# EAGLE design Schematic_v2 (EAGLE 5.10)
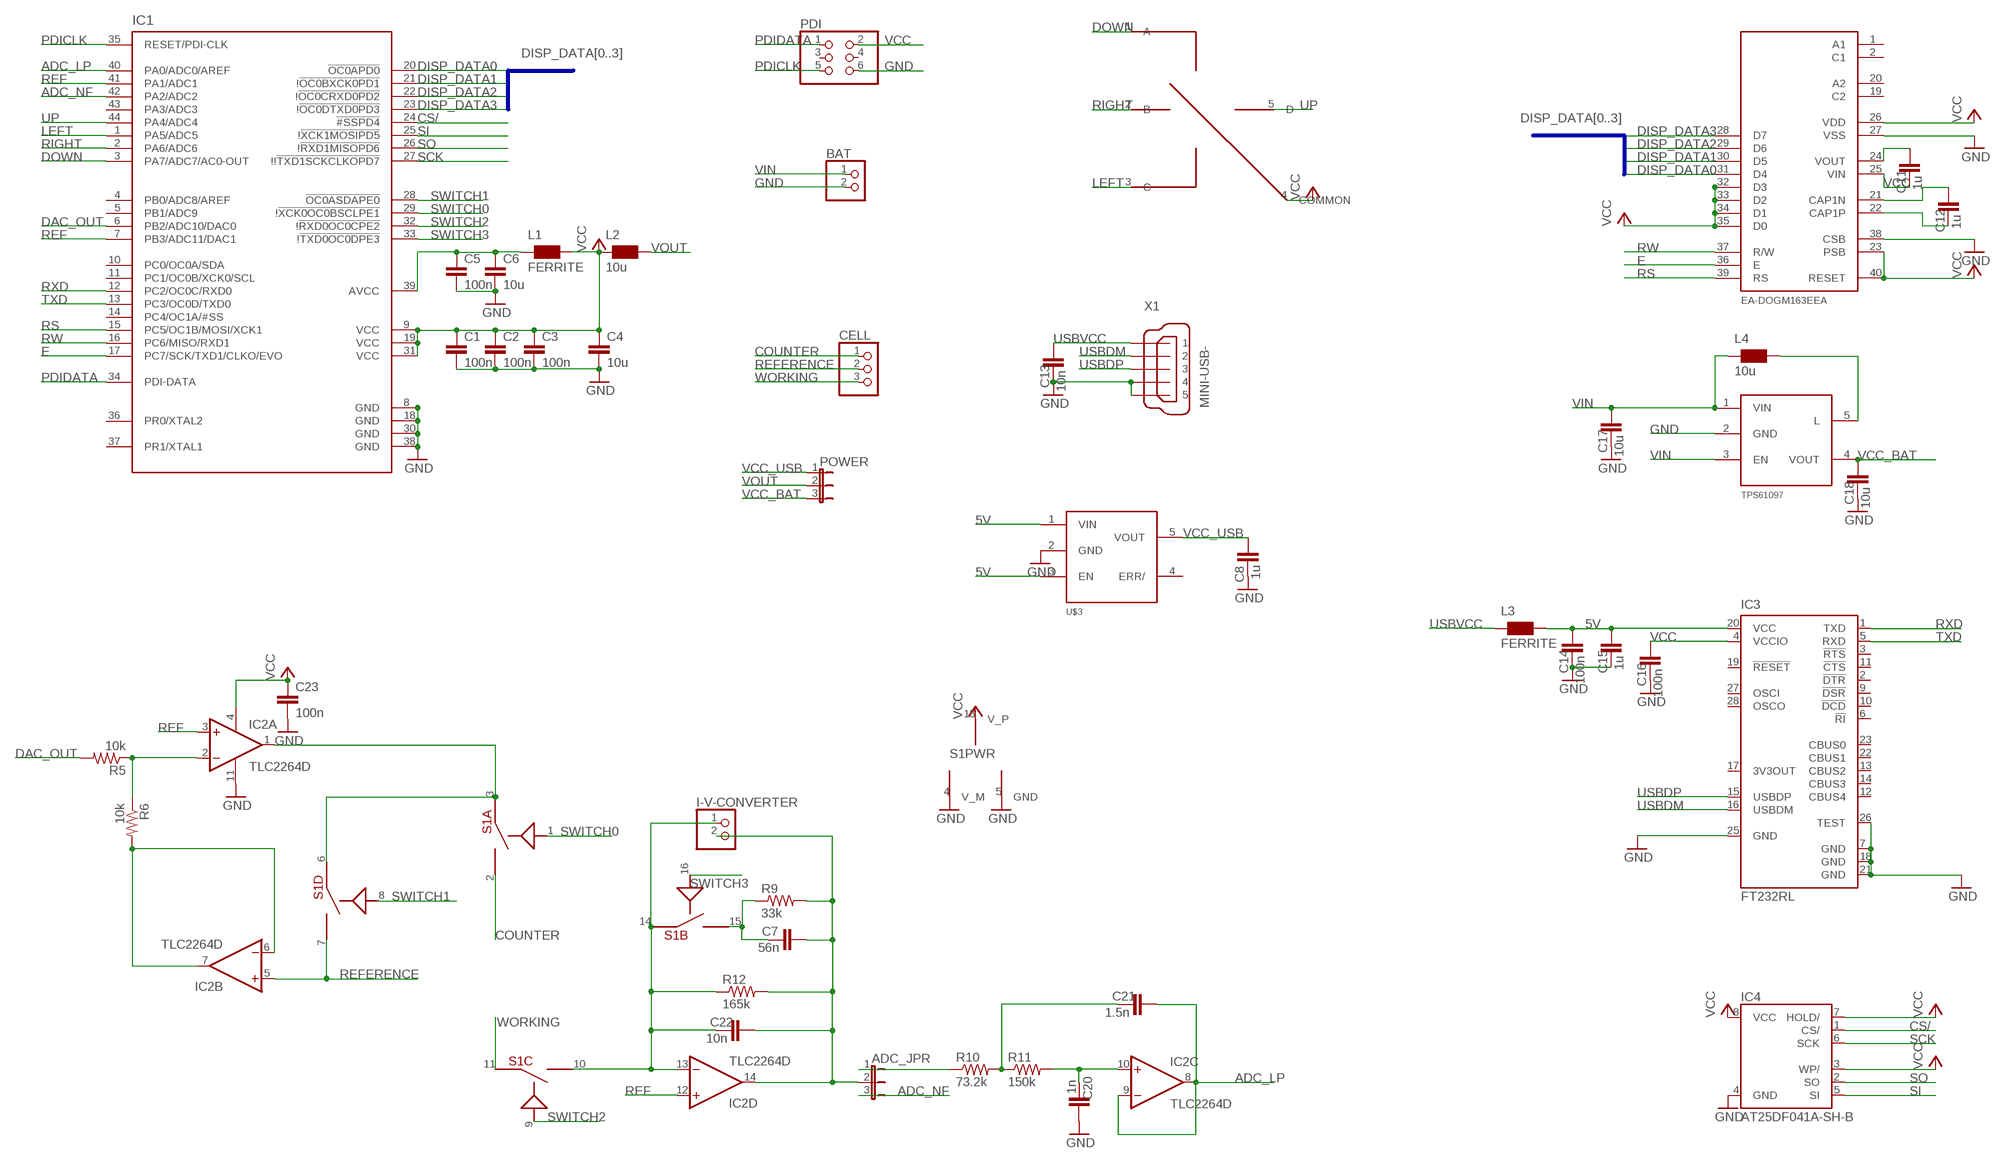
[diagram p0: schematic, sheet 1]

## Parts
ADC_JPR  JP2E  [JP2]
BAT  PINHD-1X2  [1X02]
C1  100n  C-EUC0805  [C0805]
C2  100n  C-EUC0805  [C0805]
C3  100n  C-EUC0805  [C0805]
C4  10u  C-EUC0805  [C0805]
C5  100n  C-EUC0805  [C0805]
C6  10u  C-EUC0805  [C0805]
C7  56n  C-EUC0805  [C0805]
C8  1u  C-EUC0805  [C0805]
C11  1u  C-EUC0805  [C0805]
C12  1u  C-EUC0805  [C0805]
C13  10n  C-EUC0805  [C0805]
C14  100n  C-EUC0805  [C0805]
C15  1u  C-EUC0805  [C0805]
C16  100n  C-EUC0805  [C0805]
C17  10u  C-EUC0805  [C0805]
C18  10u  C-EUC0805  [C0805]
C20  1n  C-EUC0805  [C0805]
C21  1.5n  C-EUC0805  [C0805]
C22  10n  C-EUC0805  [C0805]
C23  100n  C-EUC0805  [C0805]
CELL  PINHD-1X3  [1X03]
I-V-CONVERTER  PINHD-1X2  [1X02]
IC1  AT-XMEGA-XXA4-AU  [QFP80P1200X1200X120-44N]
IC2  TLC2264D  [SO14]
IC3  FT232RL  [SSOP28]
IC4  AT25DF041A-SH-B  [SOIC8]
L1  FERRITE  WE-KIHQ_0805  [WE-KI_0805_B]
L2  10u  WE-KIHQ_0805  [WE-KI_0805_B]
L3  FERRITE  WE-KIHQ_0805  [WE-KI_0805_B]
L4  10u  WE-KIHQ_0805  [WE-KI_0805_B]
PDI  PINHD-2X3  [2X03]
POWER  JP2E  [JP2]
R5  10k  R-US_R0805  [R0805]
R6  10k  R-US_R0805  [R0805]
R9  33k  R-US_R0805  [R0805]
R10  73.2k  R-US_R0805  [R0805]
R11  150k  R-US_R0805  [R0805]
R12  165k  R-US_R0805  [R0805]
S1  DG612  [SOIC16]
TPS61097  DC-DCCONVERTER  [SOT23-5]
U$1  EA_DOG-M_DISPLAY  [E_DOG-M_DISPLAY]
U$2  4DIRSWITCH  [4DIRSWITCH]
U$3  FAN2501  [SOT23-5]
X1  MINI-USB-  [USB-CUSTOM]

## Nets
5V: C14.1 C15.1 IC3.20(VCC) L3.1 U$3.1(VIN) U$3.3(EN)
ADC_LP: C21.1 IC1.40(PA0/ADC0/AREF) IC2.8(C:OUT) IC2.9(C:-IN)
ADC_NF: ADC_JPR.3 IC1.42(PA2/ADC2)
COUNTER: CELL.1 S1.2(A:D)
CS/: IC1.24(!#SSPD4) IC4.1(CS/)
DAC_OUT: IC1.6(PB2/ADC10/DAC0) R5.2
DISP_DATA0: IC1.20(!OC0APD0) U$1.31(D4)
DISP_DATA1: IC1.21(!!OC0BXCK0PD1) U$1.30(D5)
DISP_DATA2: IC1.22(!!OC0CRXD0PD2) U$1.29(D6)
DISP_DATA3: IC1.23(!!OC0DTXD0PD3) U$1.28(D7)
DOWN: IC1.3(PA7/ADC7/AC0-OUT) U$2.1(A)
E: IC1.17(PC7/SCK/TXD1/CLKO/EVO) U$1.36(E)
GND: BAT.2 C1.2 C2.2 C3.2 C4.2 C5.2 C6.2 C8.2 C13.2 C14.2 C15.2 C16.2 C17.2 C18.2 C20.1 C23.2 IC1.8(GND) IC1.18(GND) IC1.30(GND) IC1.38(GND) IC2.11(P:V-) IC3.7(GND) IC3.18(GND) IC3.21(GND) IC3.25(GND) IC3.26(TEST) IC4.4(GND) PDI.6 S1.4(PWR:V_M) S1.5(PWR:GND) TPS61097.2(GND) U$1.27(VSS) U$1.38(CSB) U$3.2(GND) X1.4 X1.5
LEFT: IC1.1(PA5/ADC5) U$2.3(C)
N$3: ADC_JPR.2 C7.1 C22.1 I-V-CONVERTER.2 IC2.14(D:OUT) R9.2 R12.2
N$4: IC2.6(B:-IN) IC2.7(B:OUT) R6.2
N$5: C5.1 C6.1 IC1.39(AVCC) L1.2
N$6: C7.2 R9.1 S1.15(B:D)
N$7: C11.1 U$1.24(VOUT)
N$8: IC2.2(A:-IN) R5.1 R6.1
N$9: C12.1 U$1.21(CAP1N)
N$10: L4.1 TPS61097.5(L)
N$12: C22.2 I-V-CONVERTER.1 IC2.13(D:-IN) R12.1 S1.10(C:D) S1.14(B:S)
N$14: C12.2 U$1.22(CAP1P)
N$16: ADC_JPR.1 R10.1
N$17: C20.2 IC2.10(C:+IN) R11.2
N$19: IC2.1(A:OUT) S1.3(A:S) S1.6(D:S)
N$20: C21.2 R10.2 R11.1
PDICLK: IC1.35(RESET/PDI-CLK) PDI.5
PDIDATA: IC1.34(PDI-DATA) PDI.1
REF: IC1.7(PB3/ADC11/DAC1) IC1.41(PA1/ADC1) IC2.3(A:+IN) IC2.12(D:+IN)
REFERENCE: CELL.2 IC2.5(B:+IN) S1.7(D:D)
RIGHT: IC1.2(PA6/ADC6) U$2.2(B)
RS: IC1.15(PC5/OC1B/MOSI/XCK1) U$1.39(RS)
RW: IC1.16(PC6/MISO/RXD1) U$1.37(R/W)
RXD: IC1.12(PC2/OC0C/RXD0) IC3.1(TXD)
SCK: IC1.27(!!!TXD1SCKCLKOPD7) IC4.6(SCK)
SI: IC1.25(!!XCK1MOSIPD5) IC4.5(SI)
SO: IC1.26(!!RXD1MISOPD6) IC4.2(SO)
SWITCH0: IC1.29(!!XCK0OC0BSCLPE1) S1.1(A:IN)
SWITCH1: IC1.28(!OC0ASDAPE0) S1.8(D:IN)
SWITCH2: IC1.32(!!RXD0OC0CPE2) S1.9(C:IN)
SWITCH3: IC1.33(!!TXD0OC0DPE3) S1.16(B:IN)
TXD: IC1.13(PC3/OC0D/TXD0) IC3.5(RXD)
UP: IC1.44(PA4/ADC4) U$2.5(D)
USBDM: IC3.16(USBDM) X1.2
USBDP: IC3.15(USBDP) X1.3
USBVCC: C13.1 L3.2 X1.1
VCC: C1.1 C2.1 C3.1 C4.1 C11.2 C16.1 C23.1 IC1.9(VCC) IC1.19(VCC) IC1.31(VCC) IC2.4(P:V+) IC3.4(VCCIO) IC4.3(WP/) IC4.7(HOLD/) IC4.8(VCC) L1.1 L2.2 PDI.2 S1.13(PWR:V_P) U$1.23(PSB) U$1.25(VIN) U$1.26(VDD) U$1.32(D3) U$1.33(D2) U$1.34(D1) U$1.35(D0) U$1.40(RESET) U$2.4(COMMON)
VCC_BAT: C18.1 POWER.3 TPS61097.4(VOUT)
VCC_USB: C8.1 POWER.1 U$3.5(VOUT)
VIN: BAT.1 C17.1 L4.2 TPS61097.1(VIN) TPS61097.3(EN)
VOUT: L2.1 POWER.2
WORKING: CELL.3 S1.11(C:S)
Unconnected: IC1.4(PB0/ADC8/AREF) IC1.5(PB1/ADC9) IC1.10(PC0/OC0A/SDA) IC1.11(PC1/OC0B/XCK0/SCL) IC1.14(PC4/OC1A/#SS) IC1.36(PR0/XTAL2) IC1.37(PR1/XTAL1) IC1.43(PA3/ADC3) IC3.2(!DTR) IC3.3(!RTS) IC3.6(!RI) IC3.9(!DSR) IC3.10(!DCD) IC3.11(!CTS) IC3.12(CBUS4) IC3.13(CBUS2) IC3.14(CBUS3) IC3.17(3V3OUT) IC3.19(!RESET) IC3.22(CBUS1) IC3.23(CBUS0) IC3.27(OSCI) IC3.28(OSCO) PDI.3 PDI.4 U$1.1(A1) U$1.2(C1) U$1.19(C2) U$1.20(A2) U$3.4(ERR/)

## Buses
DISP_DATA[0..3]

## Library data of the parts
ADC_JPR POWER = jumper:JP2E: JUMPER
BAT I-V-CONVERTER = pinhead:PINHD-1X2: PIN HEADER
C1-C8 C11-C18 C20-C23 = rcl:C-EU: CAPACITOR, European symbol
CELL = pinhead:PINHD-1X3: PIN HEADER
IC1 = xmega-a4:AT-XMEGA-XXA4-AU: ATxMega a4 Serie
IC2 = linear_new:TLC2264: OP AMP
IC3 = ftdichip:FT232R: Source: http://www.ftdichip.com/Documents/DataSheets/DS_FT232R_v104.pdf
IC4 = atmel:AT25*: SPI bus serial EEPROM
L1-L4 = wuerth-elektronik:WE-KIHQ: SMD Wire Wound Ceramic Inductor WE-KIHQ
PDI = pinhead:PINHD-2X3: PIN HEADER
R5 R6 R9-R12 = rcl:R-US_: RESISTOR, American symbol
S1 = ECE188:DG612
TPS61097 = analog-devices (2):DC-DCCONVERTER
U$1 = display_ea_dog-m:EA_DOG-M_DISPLAY
U$2 = ECE188:4DIRSWITCH
U$3 = analog-devices (2):FAN2501
X1 = con-cypressindustries:MINI-USB-: MINI USB-B Conector Source: www.cypressindustries.com

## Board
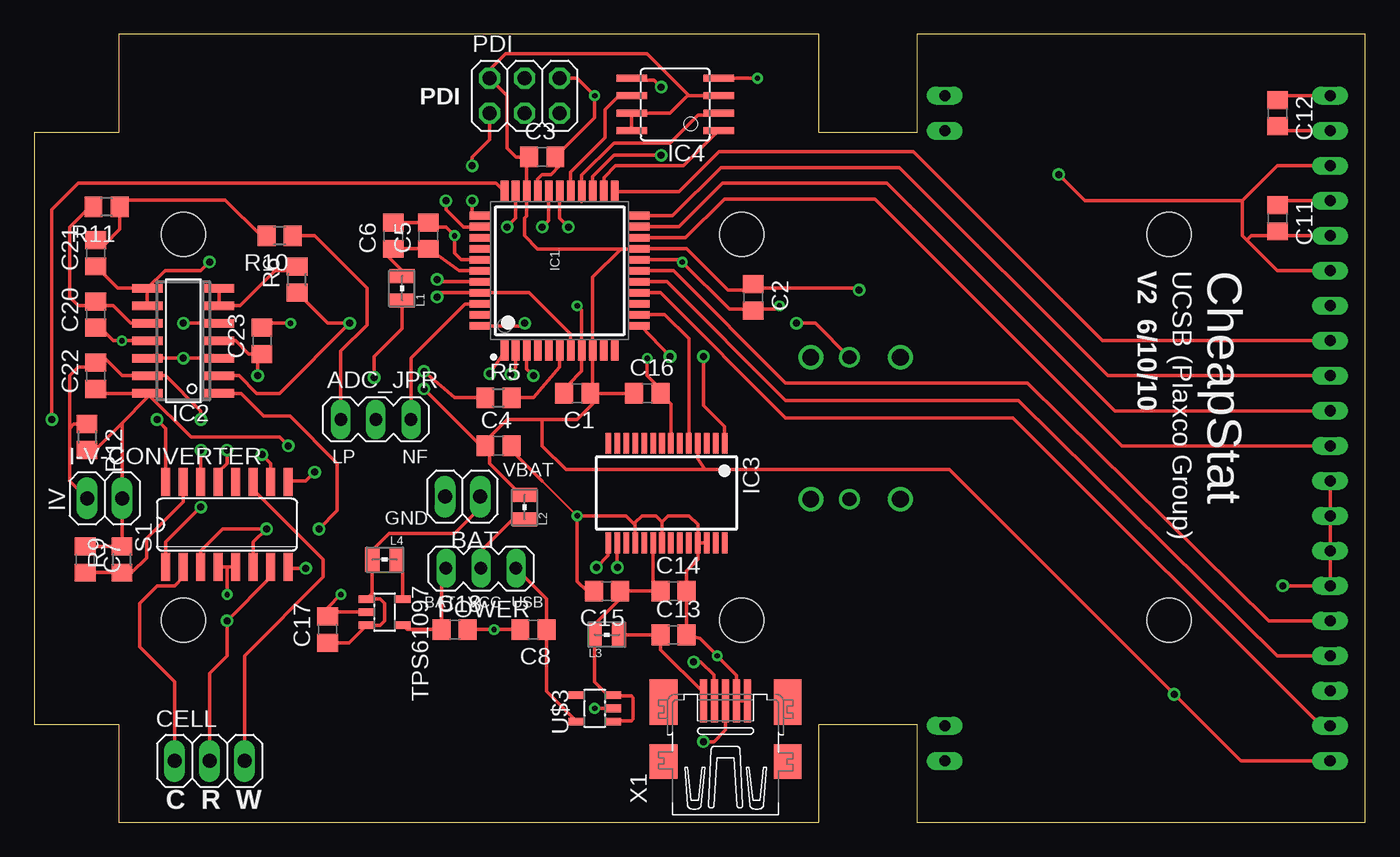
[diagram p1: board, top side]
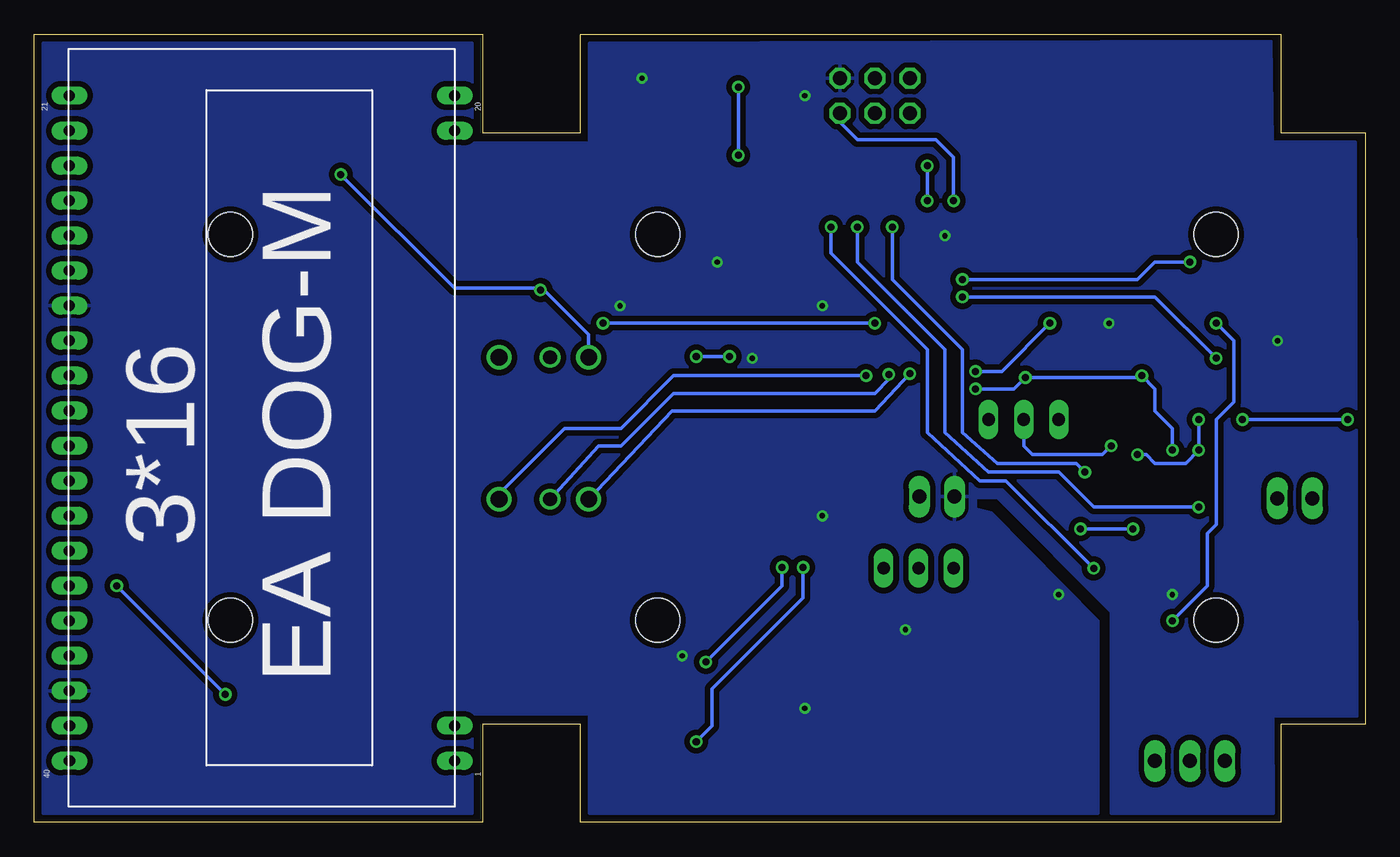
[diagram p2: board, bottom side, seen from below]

Size 96.52 x 57.15 mm. Coordinates in mm from the lower left corner, seen from the top.
Outline: 6.1,0 56.9,0 56.9,7.11 64.01,7.11 64.01,0 96.52,0 96.52,57.15 64.01,57.15 64.01,50.04 56.9,50.04 56.9,57.15 6.1,57.15 6.1,50.04 0,50.04 0,7.11 6.1,7.11 6.1,0
Copper layers (1*16): Top 0.035mm / dielectric 1.5mm / Bottom 0.035mm
Design rules "default *": minimum track width 7mil, minimum drill 15mil, track to track 7mil, track to pad 7mil, pad to pad 7mil, via to via 7mil, smd to smd 7mil, copper to edge 10mil, drill to drill 8mil, minimum pad ring 10mil, minimum via ring 8mil, stop-mask expansion 4mil, vias tented up to drill 0mil, thermal gap 10mil
Holes 3.2 mm at 10.79,14.64 82.3,42.64 82.3,14.64 10.79,42.64 51.3,42.64 51.3,14.64

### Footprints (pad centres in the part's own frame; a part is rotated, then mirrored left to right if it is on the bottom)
JP2 = drill 0.914 long: 1 -2.54,0; 2 0,0; 3 2.54,0
1X02 = drill 1.016 long: 1 -1.27,0; 2 1.27,0
C0805 = smd 1.3 x 1.5: 1 -0.95,0; 2 0.95,0
1X03 = drill 1.016 long: 1 -2.54,0; 2 0,0; 3 2.54,0
QFP80P1200X1200X120-44N = smd 1.55 x 0.55: 1 -5.75,4; 2 -5.75,3.2; 3 -5.75,2.4; 4 -5.75,1.6; 5 -5.75,0.8; 6 -5.75,0; 7 -5.75,-0.8; 8 -5.75,-1.6; 9 -5.75,-2.4; 10 -5.75,-3.2; 11 -5.75,-4; 23 5.75,-4; 24 5.75,-3.2; 25 5.75,-2.4; 26 5.75,-1.6; 27 5.75,-0.8; 28 5.75,0; 29 5.75,0.8; 30 5.75,1.6; 31 5.75,2.4; 32 5.75,3.2; 33 5.75,4 | smd 0.55 x 1.55: 12 -4,-5.75; 13 -3.2,-5.75; 14 -2.4,-5.75; 15 -1.6,-5.75; 16 -0.8,-5.75; 17 0,-5.75; 18 0.8,-5.75; 19 1.6,-5.75; 20 2.4,-5.75; 21 3.2,-5.75; 22 4,-5.75; 34 4,5.75; 35 3.2,5.75; 36 2.4,5.75; 37 1.6,5.75; 38 0.8,5.75; 39 0,5.75; 40 -0.8,5.75; 41 -1.6,5.75; 42 -2.4,5.75; 43 -3.2,5.75; 44 -4,5.75
SO14 = smd 0.6 x 2.2: 1 -3.81,-2.6; 2 -2.54,-2.6; 3 -1.27,-2.6; 4 0,-2.6; 5 1.27,-2.6; 6 2.54,-2.6; 7 3.81,-2.6; 8 3.81,2.6; 9 2.54,2.6; 10 1.27,2.6; 11 0,2.6; 12 -1.27,2.6; 13 -2.54,2.6; 14 -3.81,2.6
SSOP28 = smd 0.4 x 1.5: 1 -4.225,-3.625; 2 -3.575,-3.625; 3 -2.925,-3.625; 4 -2.275,-3.625; 5 -1.625,-3.625; 6 -0.975,-3.625; 7 -0.325,-3.625; 8 0.325,-3.625; 9 0.975,-3.625; 10 1.625,-3.625; 11 2.275,-3.625; 12 2.925,-3.625; 13 3.575,-3.625; 14 4.225,-3.625; 15 4.225,3.625; 16 3.575,3.625; 17 2.925,3.625; 18 2.275,3.625; 19 1.625,3.625; 20 0.975,3.625; 21 0.325,3.625; 22 -0.325,3.625; 23 -0.975,3.625; 24 -1.625,3.625; 25 -2.275,3.625; 26 -2.925,3.625; 27 -3.575,3.625; 28 -4.225,3.625
SOIC8 = smd 0.5 x 2.2: 1 -1.905,-3.154; 2 -0.645,-3.154; 3 0.625,-3.154; 4 1.895,-3.154; 5 1.905,3.154; 6 0.635,3.154; 7 -0.635,3.154; 8 -1.905,3.154
WE-KI_0805_B = smd 1.02 x 1.78: 1 -0.89,0; 2 0.89,0
2X03 = drill 1.016 octagon: 1 -2.54,-1.27; 2 -2.54,1.27; 3 0,-1.27; 4 0,1.27; 5 2.54,-1.27; 6 2.54,1.27
R0805 = smd 1.3 x 1.5: 1 -0.95,0; 2 0.95,0
SOIC16 = smd 0.66 x 2.032: 1 -4.445,-3.073; 2 -3.175,-3.073; 3 -1.905,-3.073; 4 -0.635,-3.073; 5 0.635,-3.073; 6 1.905,-3.073; 7 3.175,-3.073; 8 4.445,-3.073; 9 4.445,3.073; 10 3.175,3.073; 11 1.905,3.073; 12 0.635,3.073; 13 -0.635,3.073; 14 -1.905,3.073; 15 -3.175,3.073; 16 -4.445,3.073
SOT23-5 = smd 0.55 x 1.2: 1 -0.95,-1.3; 2 0,-1.3; 3 0.95,-1.3; 4 0.95,1.3; 5 -0.95,1.3
E_DOG-M_DISPLAY = drill 0.8 long: 1 3.334,0; 2 5.874,0; 19 49.054,0; 20 51.594,0; 21 51.594,27.94; 22 49.054,27.94; 23 46.514,27.94; 24 43.974,27.94; 25 41.434,27.94; 26 38.894,27.94; 27 36.354,27.94; 28 33.814,27.94; 29 31.274,27.94; 30 28.734,27.94; 31 26.194,27.94; 32 23.654,27.94; 33 21.114,27.94; 34 18.574,27.94; 35 16.034,27.94; 36 13.494,27.94; 37 10.954,27.94; 38 8.414,27.94; 39 5.874,27.94; 40 3.334,27.94
4DIRSWITCH = drill 1.2 round: 1 -5.15,6.05; 3 -5.15,-0.45; 4 5.15,-0.45; 6 5.15,6.05 | drill 1 round: 2 -5.15,2.35; 5 5.15,2.35
USB-CUSTOM = smd 3.1 x 0.5: 1 5.5,4.3; 2 5.5,3.5; 3 5.5,2.7; 4 5.5,1.9; 5 5.5,1.1 | smd 2.5 x 2: M1 1.1,-1.8; M2 1.1,7.2 | smd 3.3 x 2: M3 5.4,7.2; M4 5.4,-1.8

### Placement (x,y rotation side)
ADC_JPR  24.77,29.21 0 top
BAT  31.05,23.61 180 top
C1  39.37,31.11 180 top
C2  52.15,38.07 270 top
C3  36.83,48.26 0 top
C4  33.66,27.3 0 top
C5  28.57,42.55 90 top
C6  26.04,42.55 90 top
C7  3.68,19.05 270 top
C8  36.2,13.97 180 top
C11  90.17,43.81 270 top
C12  90.17,51.44 270 top
C13  46.35,13.59 0 top
C14  46.35,16.76 0 top
C15  41.53,16.76 180 top
C16  44.45,31.11 0 top
C17  21.27,13.97 90 top
C18  30.48,13.97 0 top
C20  4.45,36.83 90 top
C21  4.45,41.27 90 top
C22  4.45,32.38 90 top
C23  16.51,34.92 90 top
CELL  12.7,4.45 0 top
I-V-CONVERTER  5.08,23.5 0 top
IC1  38.1,40.01 90 top
IC2  10.79,34.92 90 top
IC3  45.85,23.88 180 top
IC4  46.48,52.07 90 top
L1  26.67,38.73 90 top
L2  35.56,22.86 90 top
L3  41.53,13.59 0 top
L4  25.4,19.05 180 top
PDI  35.56,52.7 0 top
POWER  32.38,18.41 180 top
R5  33.66,30.8 0 top
R6  19.05,39.37 90 top
R9  6.35,19.05 90 top
R10  17.78,42.55 180 top
R11  5.23,44.63 180 top
R12  3.81,27.94 270 top
S1  13.97,21.59 0 top
TPS61097  25.4,15.24 270 top
U$1  66.04,1.11 90 bottom
U$2  56.77,28.57 90 bottom
U$3  40.64,8.26 90 top
X1  52.83,3.3 90 top

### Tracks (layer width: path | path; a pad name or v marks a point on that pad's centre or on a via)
5V
  Top 0.254: U$3.1 42.04,7.37 43.31,7.37 43.43,7.49 43.43,9.02 43.31,9.14 42.04,9.14 U$3.3 41.59,9.21 40.64,10.16 L3.1 40.51,13.71 40.51,14.22 42.48,16.19 C15.1 C14.1 44.87,17.3 IC3.20
ADC_LP  (via drill 0.51)
  Top 0.254: IC2.8 6.04,38.73 C21.1 | IC2.8 IC2.9 | v12.7,40.64 12.06,40.01 9.46,40.01 IC2.8 | IC1.40 29.38,39.2 v29.21,39.37
  Bottom 0.254: v29.21,39.37 16.51,39.37 15.24,40.64 v12.7,40.64
ADC_NF
  Top 0.254: IC1.42 31.25,37.6 27.3,33.66 ADC_JPR.3
COUNTER
  Top 0.254: S1.2 10.79,17.78 10.16,17.14 8.89,17.14 7.62,15.88 7.62,12.7 10.16,10.16 CELL.1
CS/
  Top 0.254: IC1.24 41.3,46.76 42.16,47.62 47.1,47.62 IC4.1
DAC_OUT
  Top 0.254: IC1.6 38.1,33.02 36.2,30.8 R5.2
DISP_DATA0
  Top 0.254: IC1.20 47.23,42.41 50.04,45.21 60.96,45.21 78.87,27.3 U$1.31
DISP_DATA1
  Top 0.254: IC1.21 46.76,43.2 49.91,46.35 61.85,46.35 78.36,29.84 U$1.30
DISP_DATA2
  Top 0.254: IC1.22 46.29,44.01 49.78,47.5 62.74,47.5 77.85,32.38 U$1.29
DISP_DATA3
  Top 0.254: IC1.23 46.77,45.76 49.66,48.64 63.75,48.64 77.47,34.92 U$1.28
DOWN  (via drill 0.51)
  Top 0.254: IC1.3 35.7,32.88 v36.2,32.38
  Bottom 0.254: v36.2,32.38 50.16,32.38 53.98,28.57 58.05,28.57 62.82,23.81 U$2.1
E
  Top 0.254: U$1.36 89.54,14.61 89.53,14.61 72.01,31.88 54.48,31.88 46.35,40.01 IC1.17
GND  (via drill 0.38)
  Top 0.178: v39.37,22.23 36.83,24.77 | 34.29,27.3 C4.2 | C23.2 16.51,36.2 | C16.2 45.72,31.11
  Top 0.254: IC2.11 v6.35,34.92 5.71,34.92 5.08,35.56 4.76,35.56 C20.1 | IC1.18 46.83,40.8 v46.99,40.64 50.42,37.21 51.3,37.21 C2.2 51.98,37.21 53.72,37.21 53.98,37.47 | C1.2 38.73,31.43 38.73,31.75 39.7,32.72 IC1.8 39.7,37.13 v39.37,37.47 | IC3.25 IC3.26 | PDI.6 39.37,53.98 v40.64,52.7 40.64,51.12 C3.2 38.1,47.94 38.1,47.62 37.47,46.99 36.83,46.99 36.5,46.66 IC1.30 | IC1.38 30.95,40.8 30.48,41.27 v30.48,42.55 29.84,43.18 28.89,43.18 C5.2 C6.2 | 36.83,24.77 34.29,27.3 | 16.51,36.2 v18.57,36.2 | 45.72,31.11 44.45,32.38 v44.45,33.66 | 45.09,30.48 45.09,30.8 C16.2 46.17,30.34 IC3.7 | 13.97,18.52 S1.5 | 13.97,18.52 S1.4 | v13.97,16.51 13.97,18.52 | X1.5 X1.4 50.93,10.66 48.26,13.34 C13.2 C14.2 47.3,18.22 48.13,19.05 48.13,20.24 IC3.25 | IC3.25 48.12,21.6 47.5,22.23 45.97,22.23 45.52,21.77 | 45.52,21.77 IC3.21 | 45.52,21.77 45.07,22.23 44.07,22.23 43.57,21.73 IC3.18 43.57,21.58 42.93,22.23 v39.37,22.23 39.37,17.46 40.07,16.76 C15.2 | IC4.4 52.44,53.97 v52.45,53.98 | TPS61097.2 21.59,15.24 C17.2 21.27,15.56 v22.23,16.51 | U$3.2 v40.64,8.26 | C18.2 v33.34,13.97 C8.2
  other vias: 54.04,37.47 49.53,12.06
  pour Bottom (isolate 0.406): 95.89,56.52 95.89,0.64 64.77,0.64 64.77,7.87 56.26,7.87 56.26,0.64 19.37,0.64 19.37,14.61 27.11,22.42 28.26,22.73 28.26,23.56 26.67,23.56 18.41,15.24 18.41,0.64 6.67,0.64 6.69,7.7 0.61,7.67 0.71,49.33 6.74,49.33 6.82,56.64 56.26,56.52 56.26,49.28 64.77,49.28 64.77,56.52
LEFT  (via drill 0.51)
  Top 0.254: IC1.1 34.1,34.1 v33.02,32.54
  Bottom 0.254: U$2.3 50.28,29.84 35.56,29.84 v33.02,32.54
N$3  (via drill 0.51)
  Top 0.254: IC2.14 4.76,31.11 C22.1 | IC2.14 11.37,27.94 17.78,27.94 v18.41,27.3 | C7.1 R9.2 I-V-CONVERTER.2 6.35,28.96 | IC2.14 8.2,30.8 6.35,28.96 | 6.35,28.96 4.57,27.18 4,27.18 R12.2
  Bottom 0.254: ADC_JPR.2 24.77,27.3 24.13,26.67 19.05,26.67 v18.41,27.3
N$4
  Top 0.254: IC2.7 IC2.6 14.92,37.47 17.46,40.01 18.73,40.01 R6.2
N$5
  Top 0.254: IC1.39 30.8,40.01 C5.1 C6.1 25.71,41.27 25.4,41.27 26.67,40.01 L1.2
N$6
  Top 0.254: C7.2 R9.1 7.05,18.1 8.13,19.18 8.13,20.57 10.79,23.24 S1.15
N$7
  Top 0.254: U$1.24 90.49,45.09 C11.1
N$8  (via drill 0.51)
  Top 0.254: R5.1 30.48,30.8 v28.26,32.7 | IC2.2 14.86,32.38 16.13,31.11 17.78,31.11 v22.86,36.2 21.27,36.2 R6.1
  Bottom 0.254: v28.26,32.7 26.35,32.7 v22.86,36.2
N$9
  Top 0.254: U$1.21 90.49,52.71 C12.1
N$10
  Top 0.254: TPS61097.5 26.7,18.64 L4.1
N$12  (via drill 0.51)
  Top 0.254: C22.2 4.76,33.66 5.08,33.66 6.35,32.38 IC2.13 9.53,32.38 12.06,29.84 v12.06,29.21 | 3.81,33.66 4.12,33.66 C22.2 | R12.1 2.85,28.89 2.54,28.57 | 2.54,28.57 2.54,24.77 I-V-CONVERTER.1 | 3.81,33.66 3.81,33.02 3.17,33.02 2.54,32.38 2.54,28.57 | 3.81,33.66 C22.2 | v12.06,26.99 S1.14 | S1.10 17.14,26.04 v16.51,26.67
  Bottom 0.254: v12.06,29.21 v12.06,26.99 13.02,26.04 15.24,26.04 15.88,26.67 v16.51,26.67
N$14
  Top 0.254: U$1.22 90.49,50.17 C12.2
N$16
  Top 0.254: R10.1 20.32,42.55 24.13,38.73 24.13,36.07 22.23,34.16 ADC_JPR.1
N$17
  Top 0.254: IC2.10 6.99,36.2 5.71,37.47 4.76,37.47 C20.2 4.45,37.47 3.17,37.47 2.54,38.1 2.54,43.18 3.81,44.45 R11.2
N$19  (via drill 0.51)
  Top 0.254: v20.64,21.27 21.97,22.61 21.97,26.04 18.54,29.46 16.64,29.46 14.99,31.11 IC2.1 | S1.6 15.88,20.32 v16.83,21.27 13.65,21.27 12.06,19.68 S1.3
  Bottom 0.254: v16.83,21.27 v20.64,21.27
N$20
  Top 0.254: 16.51,42.55 R10.2 16.43,42.55 13.84,45.14 6.68,45.14 R11.1 6.18,43.01 5.08,41.91 4.76,41.91 C21.2
PDICLK  (via drill 0.51)
  Top 0.254: IC1.35 31.75,43.18 31.11,43.18 29.84,44.45 v29.84,45.09
  Bottom 0.254: PDI.5 38.1,50.8 36.83,49.53 31.11,49.53 29.84,48.26 v29.84,45.09
PDIDATA  (via drill 0.51)
  Top 0.254: v31.75,47.62 31.75,48.26 33.02,49.53 PDI.1 | v31.75,45.09 31.75,43.81 IC1.34
  Bottom 0.254: v31.75,45.09 v31.75,47.62
REF  (via drill 0.51)
  Top 0.254: IC2.12 v10.79,33.66 IC2.3 | v29.21,38.1 29.52,38.41 IC1.41 32.36,38.42 35.88,38.42 38.9,35.4 IC1.7
  Bottom 0.254: v29.21,38.1 15.24,38.1 v10.79,33.66
REFERENCE  (via drill 0.51)
  Top 0.254: S1.7 17.14,17.78 v13.97,14.61 13.97,12.06 12.7,10.79 CELL.2 | v10.79,36.2 IC2.5
  Bottom 0.254: v10.79,36.2 9.53,34.92 9.53,30.48 10.79,29.21 10.79,21.59 11.43,20.95 11.43,17.14 v13.97,14.61
RIGHT  (via drill 0.51)
  Top 0.254: IC1.2 34.9,32.99 v34.54,32.48
  Bottom 0.254: v34.54,32.48 34.54,32.13 35.56,31.11 50.16,31.11 53.98,27.3 55.62,27.3 U$2.2
RS
  Top 0.254: U$1.39 93.34,6.99 70.99,29.34 54.48,29.34 45.41,38.41 IC1.15
RW
  Top 0.254: IC1.16 45.88,39.2 54.48,30.61 71.37,30.61 90.17,12.06 U$1.37
RXD  (via drill 0.51)
  Top 0.254: IC1.12 44.01,36.01 v46.1,33.78 | v48.51,33.78 48.51,30.23 50.04,28.7 50.04,27.54 IC3.1
  Bottom 0.254: v48.51,33.78 v46.1,33.78
SCK
  Top 0.254: IC1.27 38.9,47.16 41.4,49.66 41.4,51.69 42.42,52.7 IC4.6
SI  (via drill 0.51)
  Top 0.254: IC1.25 40.5,46.85 42.04,48.39 v45.47,48.39 | v45.47,53.34 44.96,53.85 43.45,53.85 IC4.5
  Bottom 0.254: v45.47,48.39 v45.47,53.34
SO
  Top 0.254: 39.7,45.01 IC1.26 39.7,46.94 42.04,49.28 46.1,49.28 48.13,51.31 49.52,51.31 IC4.2
SWITCH0  (via drill 0.51)
  Top 0.254: IC1.29 37.3,43.65 v36.83,43.18 | v12.06,22.86 9.53,20.32 S1.1
  Bottom 0.254: v12.06,22.86 19.68,22.86 22.23,25.4 27.3,25.4 30.48,28.26 30.48,34.29 36.83,40.64 v36.83,43.18
SWITCH1  (via drill 0.51)
  Top 0.254: IC1.28 38.1,43.81 v38.73,43.18 | S1.8 18.41,18.41 v19.68,18.41
  Bottom 0.254: v38.73,43.18 38.73,41.27 31.75,34.29 31.75,28.26 27.94,24.77 26.04,24.77 v19.68,18.41
SWITCH2  (via drill 0.51)
  Top 0.254: IC1.32 34.9,43.84 v34.29,43.18 | v20.32,25.4 19.68,24.77 18.41,24.77 S1.9
  Bottom 0.254: v34.29,43.18 34.29,39.37 29.21,34.29 29.21,28.26 26.67,26.04 20.95,26.04 v20.32,25.4
SWITCH3  (via drill 0.51)
  Top 0.254: v8.89,29.21 9.53,28.57 S1.16 | v1.27,29.21 1.27,44.45 3.17,46.35 33.5,46.35 IC1.33
  Bottom 0.254: v1.27,29.21 v8.89,29.21
TXD
  Top 0.254: IC1.13 43.88,36.83 45.72,36.83 47.47,35.08 IC3.5
UP  (via drill 0.51)
  Top 0.254: v55.28,36.2 56.65,36.2 U$2.5 | IC1.44 35.37,36.01 v35.56,36.2
  Bottom 0.254: v35.56,36.2 v55.28,36.2
USBDM  (via drill 0.51)
  Top 0.254: IC3.16 42.27,18.5 v42.29,18.48 | v47.82,11.62 48.32,11.62 49.28,10.67 49.28,8.86 X1.2
  Bottom 0.254: v42.29,18.48 42.29,17.14 v47.82,11.62
USBDP  (via drill 0.51)
  Top 0.254: IC3.15 41.62,19.33 v40.77,18.48 | X1.3 50.13,6.7 49.28,5.84 v48.51,5.84
  Bottom 0.254: v40.77,18.48 40.77,16.26 47.37,9.65 47.37,6.99 v48.51,5.84
USBVCC
  Top 0.254: L3.2 C13.1 45.41,12.51 48.51,9.4 48.51,8.82 X1.1
VCC  (via drill 0.51)
  Top 0.178: U$1.40
  Top 0.254: U$1.23 90.17,47.63 87.63,45.09 | 87.63,45.09 87.63,42.55 87.95,42.23 | 87.95,42.23 90.17,40.01 U$1.26 | C1.1 40.5,31.3 IC1.9 40.5,39.55 42.55,41.59 | IC2.4 14.61,34.92 15.55,33.98 C23.1 16.19,33.66 v16.19,32.38 | 42.55,41.59 36.51,41.59 35.56,42.55 35.56,43.81 35.7,43.95 IC1.31 35.7,48.08 C3.1 34.92,48.26 34.29,48.9 34.29,52.7 PDI.2 33.02,54.61 34.16,55.75 44.45,55.75 47.5,52.7 | 42.55,41.59 43.84,41.59 IC1.19 47.3,41.6 50.29,38.61 51.55,38.61 C2.1 51.69,38.73 59.82,38.73 v59.82,38.61 | 87.63,45.09 76.2,45.09 v74.3,46.99 | 33.02,26.99 33.02,27.94 34.29,29.21 36.83,29.21 | 36.83,29.21 39.37,29.21 40.64,30.48 40.64,30.8 C1.1 | 36.83,29.21 36.83,27.3 38.54,25.59 48.64,25.59 | v13.97,26.99 13.97,26.04 13.34,25.4 S1.13 | v28.26,31.43 32.06,27.62 32.38,27.62 C4.1 33.02,26.99 | C1.1 C16.1 | C11.2 90.49,42.55 U$1.25 88.27,42.55 87.95,42.23 | U$1.32 U$1.33 U$1.34 U$1.35 v90.55,17.15 v90.55,17.14 | IC4.8 IC4.7 46.1,51.44 47.37,52.7 47.5,52.7 | IC3.4 48.12,26.36 48.64,25.59 | 48.64,25.59 66.36,25.59 v82.68,9.27 87.5,4.45 U$1.40 | IC4.3 49.63,52.7 47.5,52.7 | 24.7,32.19 v24.64,32.26 24.64,33.78 26.67,35.81 L1.1 | L2.2 35.3,23.75 33.02,26.04 33.02,26.99
  Bottom 0.254: v13.97,26.99 13.97,28.57 15.24,29.84 15.24,31.43 v16.19,32.38 16.32,32.26 v24.64,32.26 25.46,31.43 v28.26,31.43 | U$2.4 56.33,35.38 59.63,38.67 | 59.63,38.67 59.69,38.73 66.04,38.73 v74.3,46.99 | v59.82,38.61 59.69,38.61 59.63,38.67 | v82.68,9.27 v90.55,17.14
VCC_BAT
  Top 0.254: TPS61097.4 27.02,13.97 C18.1 29.53,18.1 POWER.3
VCC_USB
  Top 0.254: POWER.1 37.15,16.2 C8.1 37.15,9.5 U$3.5
VIN
  Top 0.254: C17.1 22.83,13.02 TPS61097.3 25.09,14.29 25.4,14.61 25.4,15.88 25.09,16.19 TPS61097.1 24.51,16.6 L4.2 24.45,19.11 24.45,19.68 25.72,20.95 30.48,20.95 32.33,22.8 BAT.1
VOUT
  Top 0.254: L2.1 34.67,21.97 32.38,19.68 POWER.2
WORKING
  Top 0.254: S1.11 15.88,24.13 20.95,19.05 20.95,17.78 15.24,12.06 CELL.3

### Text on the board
tPlace: PDI | V2 | UCSB (Plaxco Group) | CheapStat | 6/10/10 | LP | NF | VBAT | IV | GND | BAT | VCC | USB | C | R | W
